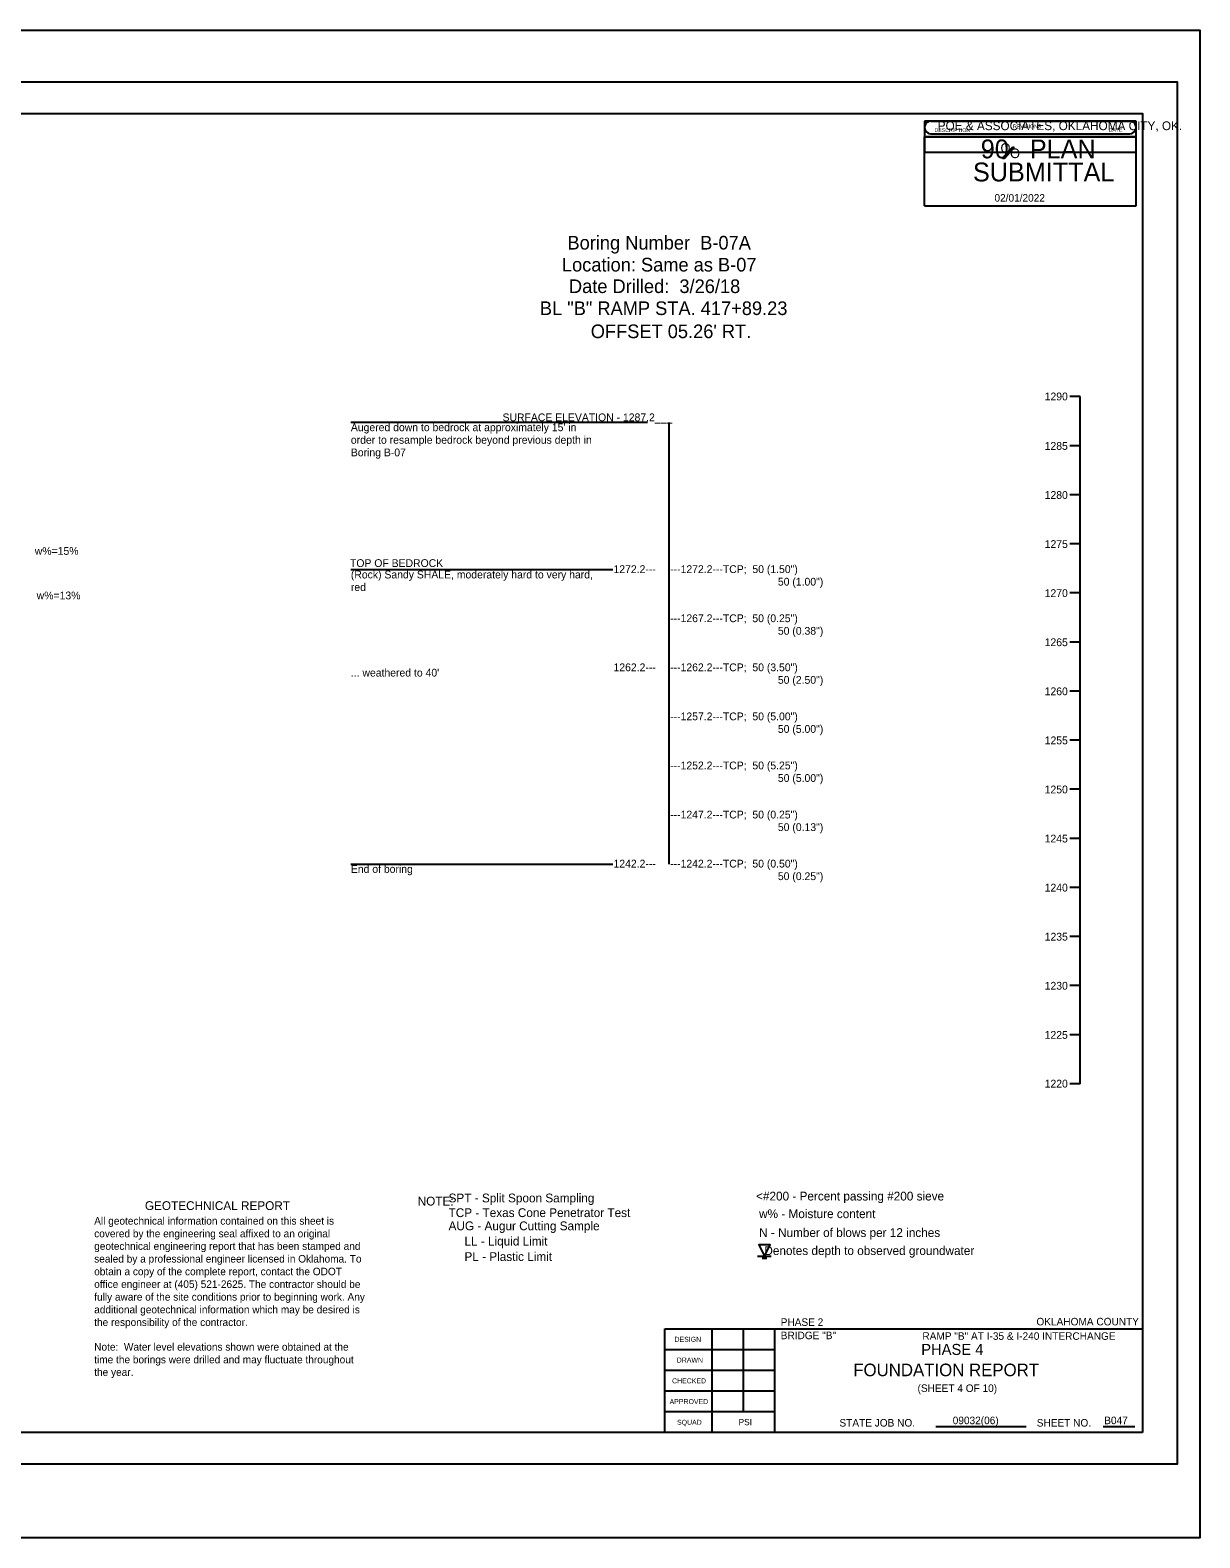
# Model space of a CAD drawing. Extents: x 2150162 to 2150245, y 143729 to 143865.
# Drawn here: x 2150182.18 to 2150200.79, y 143758.59 to 143782.59 of the extents above; entities that cross this region are included whole.
import ezdxf

# ---------------------------------------------------------------- set-up
doc = ezdxf.new("R2010")
doc.units = 0
for name, color, linetype in [('Default', 7, 'Continuous'), ('SHT_Plot_Shape_Full', 7, 'Continuous'), ('SHT_Plot_Shape_Half', 7, 'Continuous'), ('SHT_Sheet_Border', 7, 'Continuous'), ('SHT_Stamp_90_Submit', 7, 'Continuous'), ('SHT_Stamp_Rev_Block', 7, 'Continuous'), ('SHT_Standard_Sheet_Lines', 7, 'Continuous'), ('SHT_Standard_Sheet_Txt', 7, 'Continuous'), ('T', 7, 'Continuous'), ('T-Title', 7, 'Continuous'), ('Text', 7, 'Continuous')]:
    doc.layers.add(name, color=color, linetype=linetype)

# ---------------------------------------------------------------- blocks, each defined once
blk = doc.blocks.new('DGRFC_WTLEV1')
at = {"layer": 'Default'}
for points in [[(-0.0127, 0), (0.0127, 0)], [(0, 0), (0.0106, 0.0212), (-0.0106, 0.0212), (0, 0)], [(-0.0042, -0.0042), (0.0042, -0.0042)]]:
    blk.add_lwpolyline(points, dxfattribs=at)

msp = doc.modelspace()

# ---------------------------------------------------------------- linework, layer by layer
at = {"layer": 'Default'}
msp.add_line((2150198.886, 143765.823), (2150198.886, 143776.761), dxfattribs=at)
for points in [[(2150198.886, 143776.761), (2150198.72, 143776.761)], [(2150187.28, 143776.352), (2150192.003, 143776.352)], [(2150192.338, 143776.351), (2150192.338, 143769.32)], [(2150198.886, 143775.979), (2150198.72, 143775.979)], [(2150198.886, 143775.198), (2150198.72, 143775.198)], [(2150198.886, 143774.417), (2150198.72, 143774.417)], [(2150198.886, 143774.417), (2150198.72, 143774.417)], [(2150187.28, 143774.008), (2150191.447, 143774.008)], [(2150198.886, 143773.636), (2150198.72, 143773.636)], [(2150198.886, 143772.854), (2150198.72, 143772.854)], [(2150198.886, 143772.073), (2150198.72, 143772.073)], [(2150198.886, 143771.292), (2150198.72, 143771.292)], [(2150198.886, 143770.511), (2150198.72, 143770.511)], [(2150198.886, 143769.729), (2150198.72, 143769.729)], [(2150187.28, 143769.321), (2150191.447, 143769.321)], [(2150198.886, 143768.948), (2150198.72, 143768.948)], [(2150198.886, 143768.167), (2150198.72, 143768.167)], [(2150198.886, 143767.386), (2150198.72, 143767.386)], [(2150198.886, 143766.604), (2150198.72, 143766.604)], [(2150198.886, 143765.823), (2150198.72, 143765.823)]]:
    msp.add_lwpolyline(points, dxfattribs=at)
at = {"layer": 'SHT_Plot_Shape_Full'}
msp.add_lwpolyline([(2150164.792, 143782.595), (2150200.792, 143782.595), (2150200.792, 143758.595), (2150164.792, 143758.595)], close=True, dxfattribs=at)
at = {"layer": 'SHT_Plot_Shape_Half'}
msp.add_lwpolyline([(2150166.429, 143781.77), (2150200.429, 143781.77), (2150200.429, 143759.77), (2150166.429, 143759.77)], close=True, dxfattribs=at)
at = {"layer": 'SHT_Sheet_Border'}
for p, q in [((2150194.029, 143760.27), (2150194.029, 143761.921)), ((2150192.279, 143760.27), (2150192.279, 143761.92)), ((2150192.279, 143761.92), (2150199.879, 143761.92))]:
    msp.add_line(p, q, dxfattribs=at)
msp.add_lwpolyline([(2150199.879, 143760.27), (2150168.379, 143760.27), (2150168.379, 143781.27), (2150199.879, 143781.27)], close=True, dxfattribs=at)
at = {"layer": 'SHT_Stamp_90_Submit'}
for p, q in [((2150196.51, 143781.146), (2150199.676, 143781.146)), ((2150196.41, 143780.896), (2150199.776, 143780.896)), ((2150196.41, 143779.797), (2150196.41, 143780.896)), ((2150196.51, 143780.946), (2150199.676, 143780.946)), ((2150199.776, 143779.797), (2150199.776, 143780.896)), ((2150197.653, 143780.557), (2150197.809, 143780.73)), ((2150197.671, 143780.557), (2150197.827, 143780.73)), ((2150197.676, 143780.557), (2150197.832, 143780.73)), ((2150197.684, 143780.557), (2150197.839, 143780.73)), ((2150197.809, 143780.73), (2150197.839, 143780.73)), ((2150197.653, 143780.557), (2150197.684, 143780.557)), ((2150196.41, 143779.797), (2150199.776, 143779.797))]:
    msp.add_line(p, q, dxfattribs=at)
for centre, start, end in [((2150196.51, 143781.046), 89.9952, 270), ((2150199.676, 143781.046), 270, 90.0048)]:
    msp.add_arc(centre, 0.1, start, end, dxfattribs=at)
at = {"layer": 'SHT_Stamp_Rev_Block'}
for p, q in [((2150196.41, 143781.146), (2150196.41, 143780.646)), ((2150199.776, 143781.146), (2150196.41, 143781.146)), ((2150199.776, 143780.646), (2150199.776, 143781.146)), ((2150199.776, 143780.896), (2150196.41, 143780.896)), ((2150199.776, 143780.646), (2150196.41, 143780.646))]:
    msp.add_line(p, q, dxfattribs=at)
at = {"layer": 'SHT_Standard_Sheet_Lines'}
for p, q in [((2150193.029, 143760.27), (2150193.029, 143761.921)), ((2150193.529, 143760.6), (2150193.529, 143761.921)), ((2150196.59, 143760.366), (2150198.03, 143760.366)), ((2150199.255, 143760.366), (2150199.757, 143760.366))]:
    msp.add_line(p, q, dxfattribs=at)
for points in [[(2150194.029, 143761.59), (2150192.279, 143761.59)], [(2150194.029, 143761.26), (2150192.279, 143761.26)], [(2150194.029, 143760.93), (2150192.279, 143760.93)], [(2150194.029, 143760.6), (2150192.279, 143760.6)]]:
    msp.add_lwpolyline(points, dxfattribs=at)

# ---------------------------------------------------------------- block references
at = {"layer": 'Default', "xscale": 8.503919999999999, "yscale": 8.503919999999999}
msp.add_blockref('DGRFC_WTLEV1', (2150193.862, 143763.08), dxfattribs=at)

# ---------------------------------------------------------------- texts
at = {"layer": 'Default'}
for s, height, p in [('Boring Number  B-07A', 0.217, (2150190.727, 143779.103)), ('Location: Same as B-07', 0.217, (2150190.639, 143778.753)), ('Date Drilled:  3/26/18', 0.217, (2150190.751, 143778.41)), ('BL "B" RAMP STA. 417+89.23', 0.217, (2150190.288, 143778.06)), ("OFFSET 05.26' RT.", 0.217, (2150191.098, 143777.692)), ('1290', 0.124, (2150198.322, 143776.702)), ("Augered down to bedrock at approximately 15' in", 0.124, (2150187.28, 143776.211)), ('SURFACE ELEVATION - 1287.2___', 0.124, (2150189.694, 143776.369)), ('order to resample bedrock beyond previous depth in', 0.124, (2150187.28, 143776.011)), ('Boring B-07', 0.124, (2150187.28, 143775.811)), ('1285', 0.124, (2150198.322, 143775.914)), ('1280', 0.124, (2150198.322, 143775.133)), ('1275', 0.124, (2150198.322, 143774.352)), ('w%=15%', 0.124, (2150182.25, 143774.243)), ('TOP OF BEDROCK', 0.124, (2150187.266, 143774.049)), ('(Rock) Sandy SHALE, moderately hard to very hard,', 0.124, (2150187.28, 143773.867)), ('1272.2---', 0.124, (2150191.46, 143773.953)), ('---1272.2---TCP;  50 (1.50")', 0.124, (2150192.362, 143773.953)), ('red', 0.124, (2150187.28, 143773.667)), ('50 (1.00")', 0.124, (2150194.076, 143773.753)), ('1270', 0.124, (2150198.322, 143773.571)), ('w%=13%', 0.124, (2150182.28, 143773.534)), ('---1267.2---TCP;  50 (0.25")', 0.124, (2150192.362, 143773.171)), ('50 (0.38")', 0.124, (2150194.076, 143772.971)), ('1265', 0.124, (2150198.322, 143772.789)), ('1262.2---', 0.124, (2150191.46, 143772.39)), ('---1262.2---TCP;  50 (3.50")', 0.124, (2150192.362, 143772.39)), ("... weathered to 40'", 0.124, (2150187.28, 143772.305)), ('50 (2.50")', 0.124, (2150194.076, 143772.19)), ('1260', 0.124, (2150198.322, 143772.008)), ('---1257.2---TCP;  50 (5.00")', 0.124, (2150192.362, 143771.609)), ('50 (5.00")', 0.124, (2150194.076, 143771.409)), ('1255', 0.124, (2150198.322, 143771.227)), ('---1252.2---TCP;  50 (5.25")', 0.124, (2150192.362, 143770.828)), ('50 (5.00")', 0.124, (2150194.076, 143770.628)), ('1250', 0.124, (2150198.322, 143770.446)), ('---1247.2---TCP;  50 (0.25")', 0.124, (2150192.362, 143770.046)), ('50 (0.13")', 0.124, (2150194.076, 143769.846)), ('1245', 0.124, (2150198.322, 143769.664)), ('1242.2---', 0.124, (2150191.46, 143769.265)), ('---1242.2---TCP;  50 (0.50")', 0.124, (2150192.362, 143769.265)), ('End of boring', 0.124, (2150187.28, 143769.18)), ('50 (0.25")', 0.124, (2150194.076, 143769.065)), ('1240', 0.124, (2150198.322, 143768.883)), ('1235', 0.124, (2150198.322, 143768.102)), ('1230', 0.124, (2150198.322, 143767.321)), ('1225', 0.124, (2150198.322, 143766.539)), ('1220', 0.124, (2150198.322, 143765.763))]:
    msp.add_text(s, height=height, dxfattribs=at).set_placement(p)
at = {"layer": 'Defpoints'}
msp.add_text('PHASE 4', height=0.175, dxfattribs=at).set_placement((2150196.358, 143761.507))
at = {"layer": 'SHT_Stamp_90_Submit'}
for s, height, p in [('POE & ASSOCIATES, OKLAHOMA CITY, OK.', 0.14, (2150196.62, 143781.003)), ('90   PLAN', 0.3, (2150197.305, 143780.554)), ('O', 0.153, (2150197.619, 143780.642)), ('O', 0.153, (2150197.771, 143780.558)), ('SUBMITTAL', 0.3, (2150197.181, 143780.187)), ('02/01/2022', 0.12, (2150197.523, 143779.865))]:
    msp.add_text(s, height=height, dxfattribs=at).set_placement(p)
at = {"layer": 'SHT_Stamp_Rev_Block'}
for s, height, p in [('DESCRIPTION', 0.05999, (2150196.57, 143780.974)), ('REVISIONS', 0.06, (2150197.818, 143781.033)), ('DATE', 0.06, (2150199.34, 143780.978))]:
    msp.add_text(s, height=height, dxfattribs=at).set_placement(p)
at = {"layer": 'SHT_Standard_Sheet_Txt'}
for s, height, p in [('DESIGN', 0.08, (2150192.431, 143761.715)), ('DRAWN', 0.08, (2150192.467, 143761.385)), ('CHECKED', 0.08, (2150192.392, 143761.054)), ('APPROVED', 0.08, (2150192.353, 143760.724)), ('STATE JOB NO.', 0.12, (2150195.056, 143760.366)), ('SHEET NO. ', 0.12, (2150198.196, 143760.366)), ('SQUAD', 0.08, (2150192.471, 143760.394))]:
    msp.add_text(s, height=height, dxfattribs=at).set_placement(p)
at = {"layer": 'T'}
for s, height, p in [('PHASE 2', 0.12, (2150194.121, 143761.969)), ('OKLAHOMA COUNTY', 0.12, (2150198.191, 143761.977)), ('BRIDGE "B"', 0.12, (2150194.121, 143761.757)), ('RAMP "B" AT I-35 & I-240 INTERCHANGE', 0.12, (2150196.376, 143761.747)), ('(SHEET 4 OF 10)', 0.12, (2150196.299, 143760.917)), ('PSI', 0.1, (2150193.449, 143760.388)), ('09032(06)', 0.12, (2150196.859, 143760.404)), ('B047', 0.12, (2150199.27, 143760.404))]:
    msp.add_text(s, height=height, dxfattribs=at).set_placement(p)
at = {"layer": 'T-Title'}
msp.add_text('FOUNDATION REPORT', height=0.2, dxfattribs=at).set_placement((2150195.276, 143761.168))
at = {"layer": 'Text'}
for s, height, p in [('    SPT - Split Spoon Sampling', 0.14, (2150188.627, 143763.935)), (' <#200 - Percent passing #200 sieve', 0.14, (2150193.677, 143763.965)), ('GEOTECHNICAL REPORT', 0.14, (2150184.002, 143763.813)), ('NOTE:', 0.14, (2150188.343, 143763.885)), ('    TCP - Texas Cone Penetrator Test', 0.14, (2150188.627, 143763.701)), ('All geotechnical information contained on this sheet is ', 0.12, (2150183.195, 143763.581)), ('    AUG - Augur Cutting Sample', 0.14, (2150188.627, 143763.491)), ('w% - Moisture content', 0.14, (2150193.777, 143763.684)), ('covered by the engineering seal affixed to an original ', 0.12, (2150183.195, 143763.379)), (' LL - Liquid Limit', 0.14, (2150189.036, 143763.248)), ('N - Number of blows per 12 inches', 0.14, (2150193.777, 143763.384)), ('geotechnical engineering report that has been stamped and ', 0.12, (2150183.195, 143763.179)), (' PL - Plastic Limit', 0.14, (2150189.036, 143763.002)), ('    Denotes depth to observed groundwater', 0.14, (2150193.653, 143763.097)), ('sealed by a professional engineer licensed in Oklahoma. To ', 0.12, (2150183.195, 143762.977)), ('obtain a copy of the complete report, contact the ODOT ', 0.12, (2150183.195, 143762.775)), ('office engineer at (405) 521-2625. The contractor should be ', 0.12, (2150183.195, 143762.573)), ('fully aware of the site conditions prior to beginning work. Any ', 0.12, (2150183.195, 143762.371)), ('additional geotechnical information which may be desired is ', 0.12, (2150183.195, 143762.169)), ('the responsibility of the contractor.', 0.12, (2150183.195, 143761.967)), ('Note:  Water level elevations shown were obtained at the ', 0.12, (2150183.195, 143761.575)), ('time the borings were drilled and may fluctuate throughout ', 0.12, (2150183.195, 143761.373)), ('the year.', 0.12, (2150183.195, 143761.173))]:
    msp.add_text(s, height=height, dxfattribs=at).set_placement(p)

doc.saveas('drawing.dxf')
